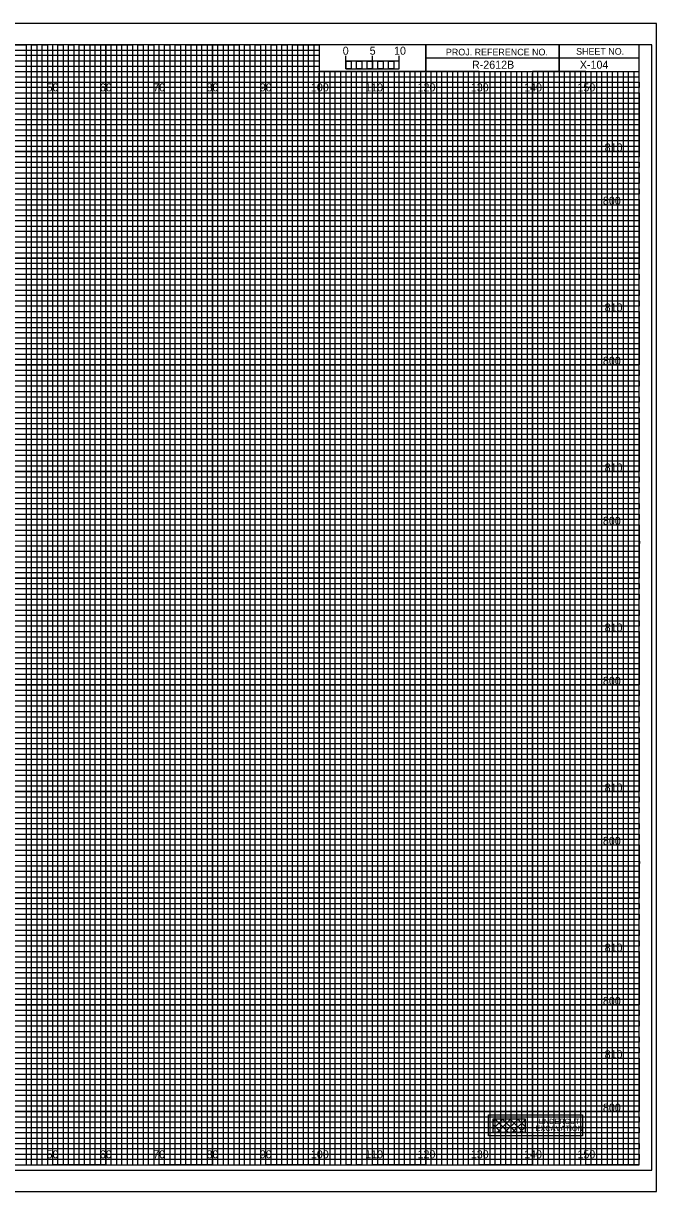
# Model space of a CAD drawing. Extents: x -13 to 323, y -5 to 214.
# Drawn here: x 204.5 to 323.3, y -5 to 214 of the extents above; entities that cross this region are included whole.
import ezdxf

# ---------------------------------------------------------------- set-up
doc = ezdxf.new("R2010")
doc.units = 0
for name, color, linetype in [('Prop Grid Mask', 7, 'Continuous'), ('Prop XS Bar Scale Labels', 7, 'Continuous'), ('Prop XS Elevation Labels', 7, 'Continuous'), ('Prop XS Offset Labels', 7, 'Continuous'), ('Prop XS Project Number', 7, 'Continuous'), ('Prop XS Sheet Number', 7, 'Continuous'), ('Prop XS Undercut Exc Hatch', 7, 'Continuous'), ('Prop XSC Text', 7, 'Continuous'), ('Sheet Cross Section CELL', 7, 'Continuous'), ('Sheet Cross Section Grid Major CELL', 7, 'Continuous'), ('Sheet Cross Section Grid Middle CELL', 7, 'Continuous'), ('Sheet Cross Section Grid Minor 1 CELL', 7, 'Continuous'), ('Sheet Cross Section Grid Minor 2 CELL', 7, 'Continuous'), ('Sheet Cross Section Scale CELL', 7, 'Continuous'), ('Sheet Cutting Line CELL', 7, 'Continuous'), ('Sheet DOT Grid CELL', 7, 'Continuous'), ('Sheet Plot Border Inside CELL', 7, 'Continuous'), ('Sheet Plot Border Outside CELL', 7, 'Continuous')]:
    doc.layers.add(name, color=color, linetype=linetype)

msp = doc.modelspace()

# ---------------------------------------------------------------- linework, layer by layer
at = {"layer": 'Prop Grid Mask'}
for points in [[(291.75, 9.4), (309.41, 9.4), (309.41, 5.47), (291.75, 5.47)], [(292.57, 6.12), (298.67, 6.12), (298.67, 8.58), (292.57, 8.58)]]:
    msp.add_lwpolyline(points, close=True, dxfattribs=at)
at = {"layer": 'Prop XS Undercut Exc Hatch'}
for p, q in [((292.57, 8.1), (293.06, 8.58)), ((292.57, 6.68), (294.47, 8.58)), ((292.57, 7.59), (294.04, 6.12)), ((292.99, 8.58), (295.45, 6.12)), ((293.42, 6.12), (295.88, 8.58)), ((294.4, 8.58), (296.87, 6.12)), ((294.83, 6.12), (297.3, 8.58)), ((295.82, 8.58), (298.28, 6.12)), ((296.25, 6.12), (298.67, 8.54)), ((297.23, 8.58), (298.67, 7.15)), ((297.66, 6.12), (298.67, 7.12)), ((298.64, 8.58), (298.67, 8.56)), ((292.57, 6.18), (292.63, 6.12))]:
    msp.add_line(p, q, dxfattribs=at)
at = {"layer": 'Sheet Cross Section CELL'}
for p, q in [((305, 210), (305, 205)), ((305, 205), (305, 210)), ((280, 207.5), (280, 205)), ((320, 207.49), (280, 207.49)), ((280, 205), (320, 205))]:
    msp.add_line(p, q, dxfattribs=at)
for points in [[(320, 210), (0, 210), (0, 0), (320, 0)], [(280, 210), (260, 210), (260, 205.03), (280, 205.03)], [(320, 210), (280, 210), (280, 205), (320, 205)]]:
    msp.add_lwpolyline(points, close=True, dxfattribs=at)
at = {"layer": 'Sheet Cross Section Grid Major CELL'}
for p, q in [((210, 210), (200, 210)), ((210, 0), (210, 210)), ((230, 210), (220, 210)), ((220, 210), (220, 0)), ((230, 0), (230, 210)), ((250, 210), (240, 210)), ((240, 210), (240, 0)), ((250, 0), (250, 210)), ((260, 210), (260, 0)), ((270, 0), (270, 205)), ((290, 205), (280, 205)), ((280, 205), (280, 0)), ((290, 0), (290, 205)), ((310, 205), (300, 205)), ((300, 205), (300, 0)), ((310, 0), (310, 205)), ((220, 0), (210, 0)), ((240, 0), (230, 0)), ((260, 0), (250, 0)), ((280, 0), (270, 0)), ((300, 0), (290, 0)), ((320, 0), (310, 0)), ((320, 0), (320, 0))]:
    msp.add_line(p, q, dxfattribs=at)
for points in [[(0, 200), (320, 200), (320, 190), (0, 190)], [(0, 180), (320, 180), (320, 170), (0, 170)], [(0, 160), (320, 160), (320, 150), (0, 150)], [(0, 140), (320, 140), (320, 130), (0, 130)], [(0, 120), (320, 120), (320, 110), (0, 110)], [(0, 100), (320, 100), (320, 90), (0, 90)], [(0, 80), (320, 80), (320, 70), (0, 70)], [(0, 60), (320, 60), (320, 50), (0, 50)], [(0, 40), (320, 40), (320, 30), (0, 30)], [(0, 20), (320, 20), (320, 10), (0, 10)]]:
    msp.add_lwpolyline(points, dxfattribs=at)
at = {"layer": 'Sheet Cross Section Grid Middle CELL'}
for points in [[(195, 210), (205, 210), (205, 0), (215, 0), (215, 210), (225, 210), (225, 0), (235, 0), (235, 210), (245, 210), (245, 0), (255, 0), (255, 210), (259.93, 210), (260, 210), (260, 205), (264.99, 205), (264.99, 0), (275, 0), (275, 205), (285, 205), (285, 0), (295, 0), (295, 205), (305, 205), (305, 0), (315, 0), (315, 205)], [(0, 205), (275, 205)], [(0, 185), (320, 185), (320, 195), (0, 195)], [(0, 165), (320, 165), (320, 175), (0, 175)], [(0, 145), (320, 145), (320, 155), (0, 155)], [(0, 125), (320, 125), (320, 135), (0, 135)], [(0, 105), (320, 105), (320, 115), (0, 115)], [(0, 85), (320, 85), (320, 95), (0, 95)], [(0, 65), (320, 65), (320, 75), (0, 75)], [(0, 45), (320, 45), (320, 55), (0, 55)], [(0, 25), (320, 25), (320, 35), (0, 35)], [(0, 5), (320, 5), (320, 15), (0, 15)]]:
    msp.add_lwpolyline(points, dxfattribs=at)
at = {"layer": 'Sheet Cross Section Grid Minor 1 CELL'}
for p, q in [((0, 209), (260, 209)), ((260, 209), (260, 207.98)), ((260, 207.98), (0, 207.98)), ((0, 207), (260, 207)), ((260, 205.89), (0, 205.89)), ((260, 207), (260, 205.89)), ((0, 204), (320, 204))]:
    msp.add_line(p, q, dxfattribs=at)
for points in [[(0, 203), (270, 203), (320, 203), (320, 202), (0, 202)], [(0, 201), (320, 201), (320, 199), (0, 199)], [(0, 198), (320, 198), (320, 197), (0, 196.98)], [(0, 196), (320, 196), (320, 194), (0, 194)], [(0, 193), (320, 193), (320, 192), (0, 192)], [(0, 191), (320, 191), (320, 189), (0, 189)], [(0, 188), (320, 188), (320, 187), (0, 187)], [(0, 186), (320, 186), (320, 184), (0, 184)], [(0, 183), (320, 183), (320, 182), (0, 182)], [(0, 181), (320, 181), (320, 179), (0, 179)], [(0, 178), (320, 178), (320, 177), (0, 177)], [(0, 176), (320, 176), (320, 173.95), (320, 173), (320, 172), (0, 172)], [(0, 174), (320, 174), (320, 173), (0, 173)], [(0, 171), (320, 171), (320, 169), (0, 169.03)], [(0, 169.03), (320, 169), (320, 168), (0, 168)], [(0, 167), (320, 167), (320, 166), (0, 166)], [(0, 164), (320, 164), (320, 163), (0, 163)], [(0, 162), (320, 162), (320, 161), (0, 161)], [(-0.07, 158.89), (320, 158.89), (320, 157.88), (-0.07, 157.88)], [(0, 157), (320, 157), (320, 156), (0, 156)], [(0, 154), (320, 154), (320, 153), (0, 153)], [(0, 152), (320, 152), (320, 151), (0, 151)], [(0, 149), (320, 149), (320, 148), (0, 148)], [(0, 147), (320, 147), (320, 146), (0, 146)], [(0, 144), (320, 144), (320, 143), (0, 143)], [(0, 142), (320, 142), (320, 141), (0, 141)], [(0, 139), (320, 139), (319.99, 137.98), (0, 138)], [(0, 137), (320, 137), (320, 136), (0, 136)], [(0, 134), (320, 134), (320, 133), (0, 133)], [(0, 132), (320, 132), (320, 131), (0, 131)], [(0, 129), (320, 129), (320, 128), (0, 128)], [(0, 127), (320, 127), (320, 126), (0, 126)], [(0, 124), (320, 124), (320, 123), (0, 123)], [(0, 122), (320, 122), (320, 121), (0, 121)], [(0, 119), (320, 119), (320, 118), (0, 118)], [(0, 116.99), (320.07, 116.91), (320, 116), (0, 116)], [(0, 114), (320, 114), (320, 113), (0, 113)], [(0, 112), (320, 112), (320, 111), (0, 111)], [(0, 109), (320, 109), (320, 108), (0, 108)], [(0, 107), (320, 107), (320, 106), (0, 106)], [(0, 104), (320, 104), (320, 103), (0, 103)], [(0, 102), (320, 102), (320, 101), (0, 101)], [(0, 99), (320, 99), (320, 98), (0, 98)], [(0, 97), (320, 97), (320, 96), (0, 96)], [(0, 94), (320, 94), (320, 93), (0, 93)], [(0, 92), (320, 92), (320, 91), (0, 91)], [(0, 89), (320, 89), (320, 88), (0, 88)], [(0, 87), (320, 87), (320, 86), (0, 86)], [(0, 84), (320, 84), (320, 83), (0, 83)], [(0, 82), (320, 82), (320, 81), (0, 81)], [(0, 79), (320, 79), (319.99, 77.98), (0, 78)], [(0, 77), (320, 77), (320, 76), (0, 76)], [(0, 74), (320, 74), (320, 73), (0, 73)], [(0, 72), (320, 72), (320, 71), (0, 71)], [(0, 69), (320, 69), (320, 68), (0, 68)], [(0, 67), (320, 67), (320, 66), (0, 66)], [(0, 64), (320, 64), (320, 63), (0, 63)], [(0, 62), (320, 62), (320, 61), (0, 61)], [(0, 59), (320, 59), (320, 58), (0, 58)], [(0, 56.99), (320.07, 56.91), (320, 56), (0, 56)], [(0, 54), (320, 54), (320, 53), (0, 53)], [(0, 52), (320, 52), (320, 51), (0, 51)], [(0, 49), (320, 49), (320, 48), (0, 48)], [(0, 47), (320, 47), (320, 46), (0, 46)], [(0, 44), (320, 44), (320, 43), (0, 43)], [(0, 42), (320, 42), (320, 41), (0, 41)], [(0, 39), (320, 39), (320, 38), (0, 38)], [(0, 37), (320, 37), (320, 36), (0, 36)], [(0, 34), (320, 34), (320, 33), (0, 33)], [(0, 32), (320, 32), (320, 31), (0, 31)], [(0, 29), (320, 29), (320, 28), (0, 28)], [(0, 27), (320, 27), (320, 26), (0, 26)], [(0, 24), (320, 24), (320, 23), (0, 23)], [(0, 22), (320, 22), (320, 21), (0, 21)], [(0, 19), (320, 19), (320, 18), (0, 18)], [(0, 17), (320, 17), (320, 16), (0, 16)], [(0, 14), (320, 14), (320, 13), (0, 13)], [(0, 12), (320, 12), (320, 11), (0, 11)], [(0, 9), (320, 9), (320, 8), (0, 8)], [(0, 7), (320, 7), (320, 6), (0, 6)], [(0, 4), (320, 4), (320, 3), (0, 3)], [(0, 2), (320, 2), (320, 1), (0, 1)]]:
    msp.add_lwpolyline(points, dxfattribs=at)
at = {"layer": 'Sheet Cross Section Grid Minor 2 CELL'}
for p, q in [((267, 205), (266.01, 205)), ((266.01, 205), (266.01, 0)), ((267, 0), (267, 205)), ((269, 205), (268, 205)), ((268, 205), (268, 0)), ((269, 0), (269, 205)), ((266.01, 0), (265, 0)), ((268, 0), (267, 0))]:
    msp.add_line(p, q, dxfattribs=at)
for points in [[(205, 0), (206, 0), (206, 210), (207, 210), (207, 0)], [(207, 0), (208, 0), (208, 210), (209, 210), (209, 0)], [(210, 0), (211, 0), (211, 210), (212, 210), (212, 0)], [(212, 0), (213, 0), (213, 210), (214, 210), (214, 0)], [(215, 0), (216, 0), (216, 210), (217, 210), (217, 0)], [(217, 0), (218, 0), (218, 210), (219, 210), (219, 0)], [(220, 0), (221, 0), (221, 210), (222, 210), (222, 0)], [(222, 0), (223, 0), (223, 210), (224, 210), (224, 0)], [(225, 0), (226, 0), (226, 210), (227, 210), (227, 0)], [(227, 0), (228, 0), (228, 210), (229, 210), (229, 0)], [(230, 0), (231, 0), (231, 210), (232, 210), (232, 0)], [(232, 0), (233, 0), (233, 210), (234, 210), (234, 0)], [(235, 0), (236, 0), (236, 210), (237, 210), (237, 0)], [(237, 0), (238, 0), (238, 210), (239, 210), (239, 0)], [(240, 0), (241, 0), (241, 210), (242, 210), (242, 0)], [(242, 0), (243, 0), (243, 210), (244, 210), (244, 0)], [(245, 0), (246, 0), (246, 210), (247, 210), (247, 0)], [(247, 0), (248, 0), (248, 210), (249, 210), (249, 0)], [(250, 0), (251, 0), (251, 210), (252, 210), (252, 0)], [(252, 0), (253, 0), (253, 210), (254, 210), (254, 0)], [(255, 0), (256, 0), (256, 210), (257, 210), (257, 0)], [(257, 0), (258, 0), (258, 210), (259, 210), (259, 0)], [(260, 0), (261, 0), (261, 205), (262.02, 205), (262.02, 0)], [(262, 0), (263, 0), (263, 205), (263.99, 205), (263.99, 0)], [(270, 0), (270.98, 0), (270.98, 205), (272, 205), (272, 0)], [(272, 0), (273, 0), (273, 205), (274.05, 205), (274.05, 0)], [(275, 0), (276, 0), (276, 205), (277, 205), (277, 0)], [(277, 0), (278, 0), (278, 205), (279, 205), (279, 0)], [(280, 0), (281, 0), (281, 205), (282, 205), (282, 0)], [(282, 0), (283, 0), (283, 205), (284, 205), (284, 0)], [(285, 0), (286, 0), (286, 205), (287, 205), (287, 0)], [(287, 0), (288, 0), (288, 205), (289, 205), (289, 0)], [(290, 0), (291, 0), (291, 205), (292, 205), (292, 0)], [(292, 0), (293, 0), (293, 205), (294, 205), (294, 0)], [(295, 0), (296, 0), (296, 205), (297, 205), (297, 0)], [(297, 0), (298, 0), (298, 205), (299, 205), (299, 0)], [(300, 0), (301, 0), (301, 205), (302, 205), (302, 0)], [(302, 0), (303, 0), (303, 205), (304, 205), (304, 0)], [(305, 0), (306, 0), (306, 205), (307, 205), (307, 0)], [(307, 0), (308, 0), (308, 205), (309, 205), (309, 0)], [(310, 0), (311, 0), (311, 205), (312, 205), (312, 0)], [(312, 0), (313, 0), (313, 205), (314, 205), (314, 0)], [(315, 0), (316, 0), (316, 205), (317, 205), (317, 0)], [(317, 0), (318, 0), (318, 205), (319, 205), (319, 0)]]:
    msp.add_lwpolyline(points, dxfattribs=at)
at = {"layer": 'Sheet Cross Section Scale CELL'}
for p, q in [((265, 205.49), (265, 207.9)), ((265, 206.9), (265, 207.9)), ((270, 205.49), (270, 207.9)), ((275, 205.49), (275, 207.9)), ((275, 206.9), (275, 207.9))]:
    msp.add_line(p, q, dxfattribs=at)
for points in [[(275, 206.9), (265, 206.9), (265, 205.49), (275, 205.49)], [(265, 206.9), (266, 206.9), (266, 205.49), (265, 205.49)], [(267, 206.9), (268, 206.9), (268, 205.49), (267, 205.49)], [(269, 206.9), (270, 206.9), (270, 205.49), (269, 205.49)], [(271, 206.9), (272, 206.9), (272, 205.49), (271, 205.49)], [(273, 206.9), (274, 206.9), (274, 205.49), (273, 205.49)]]:
    msp.add_lwpolyline(points, close=True, dxfattribs=at)
at = {"layer": 'Sheet Cutting Line CELL'}
for p, q in [((323.3, 214), (-13.4, 214)), ((-13.4, -5), (323.3, -5))]:
    msp.add_line(p, q, dxfattribs=at)
at = {"layer": 'Sheet DOT Grid CELL'}
for p, q in [((210, 0), (210, 210)), ((220, 0), (220, 210)), ((230, 0), (230, 210)), ((240, 0), (240, 210)), ((250, 0), (250, 210)), ((260, 0), (260, 204.69)), ((270, 0), (270, 204.69)), ((280, 0), (280, 204.69)), ((290, 0), (290, 204.69)), ((300, 0), (300, 204.69)), ((310, 0), (310, 204.69)), ((0, 200), (320, 200)), ((0, 190), (320, 190)), ((0, 180), (320, 180)), ((0, 170), (320, 170)), ((0, 160), (320, 160)), ((0, 150), (320, 150)), ((0, 140), (320, 140)), ((0, 130), (320, 130)), ((0, 120), (320, 120)), ((0, 110), (320, 110)), ((0, 100), (320, 100)), ((0, 90), (320, 90)), ((0, 80), (320, 80)), ((0, 70), (320, 70)), ((0, 60), (320, 60)), ((0, 50), (320, 50)), ((0, 40), (320, 40)), ((0, 30), (320, 30)), ((0, 20), (320, 20)), ((0, 10), (320, 10))]:
    msp.add_line(p, q, dxfattribs=at)
at = {"layer": 'Sheet Plot Border Inside CELL'}
msp.add_lwpolyline([(-10.8, -1), (322.4, -1), (322.4, 210), (-10.8, 210)], close=True, dxfattribs=at)
at = {"layer": 'Sheet Plot Border Outside CELL'}
msp.add_lwpolyline([(-13.4, -5), (323.3, -5), (323.3, 214), (-13.4, 214)], close=True, dxfattribs=at)

# ---------------------------------------------------------------- texts
at = {"layer": 'Prop XS Bar Scale Labels'}
for s, p in [('5', (269.47, 208.12)), ('10', (274.04, 208.12))]:
    msp.add_text(s, height=1.5, dxfattribs=at).set_placement(p)
at = {"layer": 'Prop XS Elevation Labels'}
for s, p in [('810', (313.55, 190)), ('800', (313.22, 180)), ('810', (313.55, 160)), ('800', (313.22, 150)), ('810', (313.55, 130)), ('800', (313.22, 120)), ('810', (313.55, 100)), ('800', (313.22, 90)), ('810', (313.55, 70)), ('800', (313.22, 60)), ('810', (313.55, 40)), ('800', (313.22, 30)), ('810', (313.55, 20)), ('800', (313.22, 10))]:
    msp.add_text(s, height=1.5, dxfattribs=at).set_placement(p)
at = {"layer": 'Prop XS Offset Labels'}
for s, p in [('50', (208.86, 201.25)), ('60', (218.86, 201.25)), ('70', (228.86, 201.25)), ('80', (238.86, 201.25)), ('90', (248.86, 201.25)), ('100', (258.44, 201.25)), ('110', (268.62, 201.25)), ('120', (278.44, 201.25)), ('130', (288.44, 201.25)), ('140', (298.44, 201.25)), ('150', (308.44, 201.25)), ('50', (208.86, 1.25)), ('60', (218.86, 1.25)), ('70', (228.86, 1.25)), ('80', (238.86, 1.25)), ('90', (248.86, 1.25)), ('100', (258.44, 1.25)), ('110', (268.62, 1.25)), ('120', (278.44, 1.25)), ('130', (288.44, 1.25)), ('140', (298.44, 1.25)), ('150', (308.44, 1.25))]:
    msp.add_text(s, height=1.5, dxfattribs=at).set_placement(p)
at = {"layer": 'Prop XS Project Number'}
msp.add_text('R-2612B', height=1.5, dxfattribs=at).set_placement((288.66, 205.5))
at = {"layer": 'Prop XS Sheet Number'}
msp.add_text('X-104', height=1.5, dxfattribs=at).set_placement((308.89, 205.5))
at = {"layer": 'Prop XSC Text'}
for s, p in [('EXCAVATION', (300.58, 6.36)), ('UNDERCUT', (301.11, 7.67))]:
    msp.add_text(s, height=1, dxfattribs=at).set_placement(p)
at = {"layer": 'Sheet Cross Section CELL'}
for s, p in [('PROJ. REFERENCE NO.', (283.77, 207.99)), ('SHEET NO.', (308.19, 208.12))]:
    msp.add_text(s, height=1.25, dxfattribs=at).set_placement(p)
at = {"layer": 'Sheet Cross Section Scale CELL'}
msp.add_text('0', height=1.5, dxfattribs=at).set_placement((264.41, 208.12))

doc.saveas('drawing.dxf')
